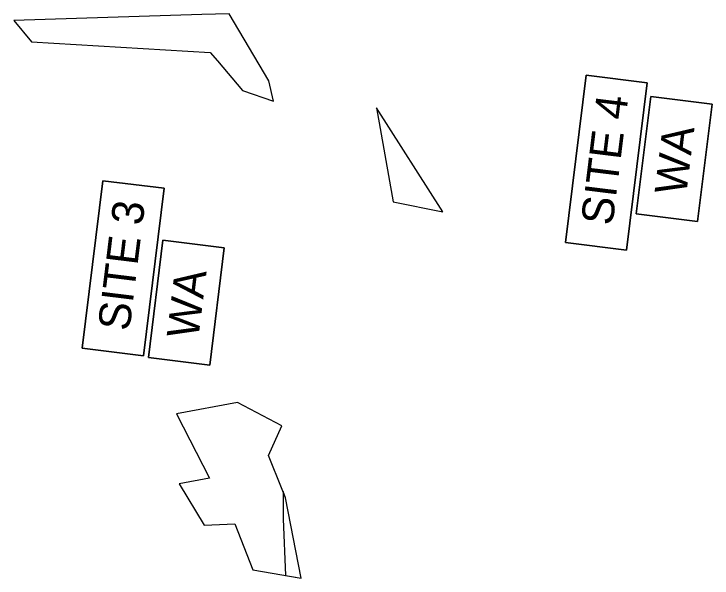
# Model space of a CAD drawing. Extents: x 474218 to 481634, y 484357 to 504997.
# Drawn here: x 481232.9 to 481562, y 491448 to 491714 of the extents above; entities that cross this region are included whole.
import ezdxf

# ---------------------------------------------------------------- set-up
doc = ezdxf.new("R2010")
doc.units = 0
for name, color, linetype in [('Old_Level_29', 7, 'Continuous'), ('Old_Level_30', 7, 'Continuous'), ('Prop Earthen Structure Fill In Wetlands Hatching CELL', 7, 'Continuous'), ('Prop Grid Mask', 7, 'Continuous'), ('Scratch_Level_4', 7, 'Continuous')]:
    doc.layers.add(name, color=color, linetype=linetype)

msp = doc.modelspace()

# ---------------------------------------------------------------- linework, layer by layer
at = {"layer": 'Old_Level_29'}
for points in [[(481492.82, 491606.14), (481502.55, 491685.11), (481531.42, 491681.55), (481521.7, 491602.59)], [(481265.07, 491556.39), (481274.79, 491635.36), (481303.67, 491631.81), (481293.94, 491552.84)]]:
    msp.add_lwpolyline(points, close=True, dxfattribs=at)
at = {"layer": 'Old_Level_30'}
for points in [[(481526.27, 491619.68), (481533.09, 491675.04), (481561.96, 491671.49), (481555.14, 491616.12)], [(481296.31, 491551.95), (481303.13, 491607.31), (481331.99, 491603.76), (481325.17, 491548.39)]]:
    msp.add_lwpolyline(points, close=True, dxfattribs=at)
at = {"layer": 'Prop Earthen Structure Fill In Wetlands Hatching CELL'}
for p, q in [((481328.8, 491691.82), (481340.66, 491677.82)), ((481337.06, 491473.57), (481345.43, 491451.85))]:
    msp.add_line(p, q, dxfattribs=at)
for points in [[(481321.43, 491713.65), (481232.9, 491710.84), (481241.13, 491700.82), (481325.42, 491695.8), (481325.42, 491695.8), (481325.42, 491695.8), (481328.8, 491691.82)], [(481340.66, 491677.82), (481355.22, 491672.87), (481353.07, 491682.49), (481334.38, 491713.96), (481321.43, 491713.65)], [(481411.63, 491625.42), (481435.01, 491620.65), (481403.75, 491669.74), (481411.63, 491625.42)], [(481359.36, 491489.79), (481352.87, 491505.73), (481359.16, 491519.77), (481338.21, 491530.84), (481309.52, 491525.39), (481325, 491495.09), (481310.79, 491492.47), (481322.5, 491472.92), (481337.06, 491473.57)], [(481345.43, 491451.85), (481368.26, 491448.02), (481360.93, 491485.89), (481359.36, 491489.79)]]:
    msp.add_lwpolyline(points, dxfattribs=at)
at = {"layer": 'Prop Grid Mask'}
for points in [[(481521.7, 491602.59), (481531.42, 491681.55), (481502.55, 491685.11), (481492.82, 491606.14)], [(481555.14, 491616.12), (481561.96, 491671.49), (481533.09, 491675.04), (481526.27, 491619.68)], [(481293.94, 491552.84), (481303.67, 491631.81), (481274.79, 491635.36), (481265.07, 491556.39)], [(481325.17, 491548.39), (481331.99, 491603.76), (481303.13, 491607.31), (481296.31, 491551.95)]]:
    msp.add_lwpolyline(points, close=True, dxfattribs=at)
at = {"layer": 'Scratch_Level_4'}
for points in [[(481411.63, 491625.42), (481435.01, 491620.65), (481403.75, 491669.74)], [(481360.92, 491449.25), (481368.26, 491448.02), (481360.93, 491485.89), (481359.75, 491488.78), (481359.81, 491475.93)]]:
    msp.add_lwpolyline(points, close=True, dxfattribs=at)

# ---------------------------------------------------------------- texts
at = {"layer": 'Old_Level_29'}
for s, p in [('SITE 4', (481515.02, 491613.88)), ('SITE 3', (481287.27, 491564.14))]:
    msp.add_text(s, height=15, rotation=82.9799, dxfattribs=at).set_placement(p)
at = {"layer": 'Old_Level_30'}
for p in [(481549.75, 491628.22), (481319.78, 491560.49)]:
    msp.add_text('WA', height=15, rotation=82.9799, dxfattribs=at).set_placement(p)

doc.saveas('drawing.dxf')
